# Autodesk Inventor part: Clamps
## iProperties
Shininess: 20.0
Created: 2001-08
Part Number: Clamps
Document SubType Name: Modeling
Designer: Mike Atwood
Material: Aluminum-6061
Density: 0.0
Volumn: 0.0
Area: 0.0
PropertySet Name: Model Information
Control State: 0
Master: False
Checked Out: False
Author: MAtwood84549
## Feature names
1. Revolution9
2. Extrusion10
3. Extrusion11
4. Fillet1
5. Fillet2
6. Extrusion12
7. Fillet3
8. Fillet4
9. Extrusion14
10. Extrusion15
11. Extrusion13
12. Extrusion16
13. Extrusion17
14. Revolution10
15. Extrusion18
16. Fillet5
17. Circular Pattern2
